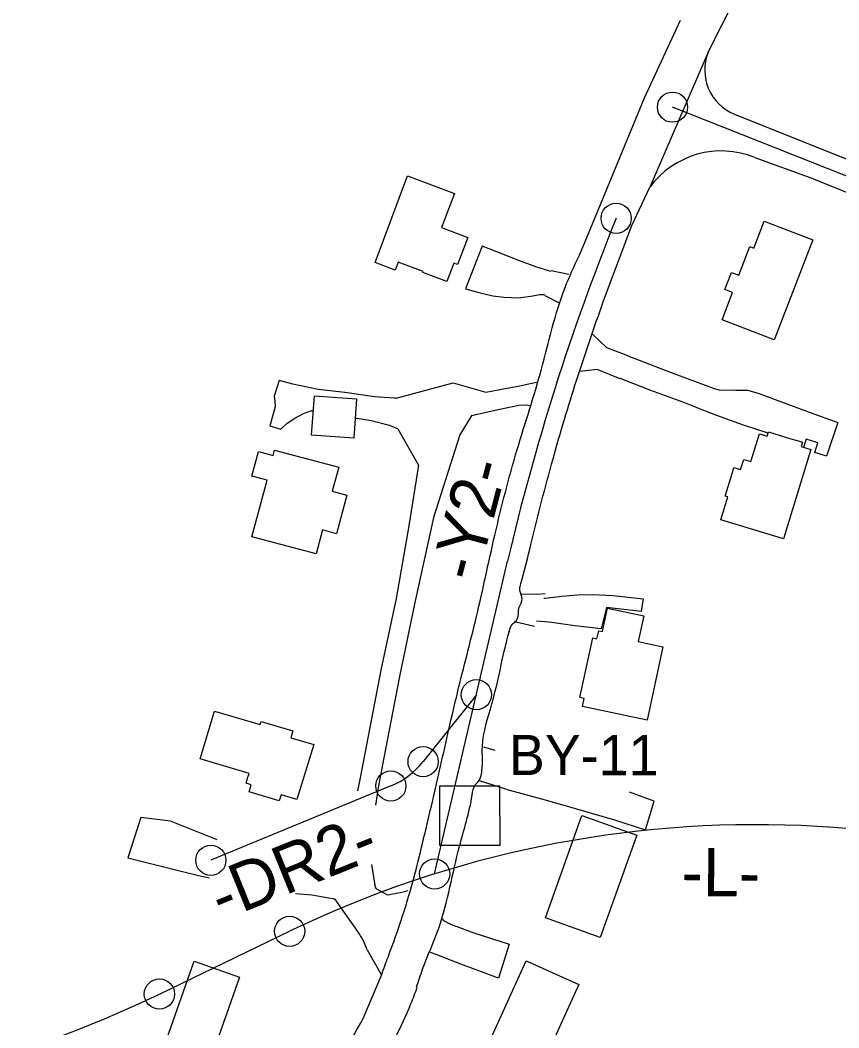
# Model space of a CAD drawing. Extents: x 2088830 to 2093930, y 861854 to 865154.
# Drawn here: x 2091262 to 2091668, y 863895 to 864396 of the extents above; entities that cross this region are included whole.
import ezdxf

# ---------------------------------------------------------------- set-up
doc = ezdxf.new("R2010")
doc.units = 0
for name, color, linetype in [('Default', 7, 'Continuous'), ('Exist Building', 7, 'Continuous'), ('Exist Building Metal Canopy', 7, 'Continuous'), ('Exist Horizontal Alignment', 7, 'Continuous'), ('Exist Horizontal Alignment Station Label', 7, 'Continuous'), ('Exist Roads EOP', 7, 'Continuous'), ('Exist Roads EOP Other', 7, 'Continuous'), ('Exist Roads Soil', 7, 'Continuous')]:
    doc.layers.add(name, color=color, linetype=linetype)

msp = doc.modelspace()

# ---------------------------------------------------------------- linework, layer by layer
at = {"layer": 'Default'}
for p, q in [((2091755.37, 864285.26), (2091585.51, 864352.73)), ((2091467.38, 863971.85), (2091503.59, 864127.14)), ((2091488.13, 864060.86), (2091461.67, 864027.62)), ((2091445.65, 864015.56), (2091356.26, 863978.63)), ((2091484.79, 864000.62), (2091484.79, 864000.62)), ((2091330.74, 863912.18), (2091395.38, 863943.36))]:
    msp.add_line(p, q, dxfattribs=at)
msp.add_lwpolyline([(2091470, 863985.91), (2091469.97, 864015.56), (2091499.67, 864015.59), (2091499.7, 863985.94)], close=True, dxfattribs=at)
for centre, radius, start, end in [((2092628.42, 863864.87), 1155, 158.0015, 166.87501), ((2091430.37, 864052.53), 40, 292.4477, 321.4722), ((2091626.97, 863463.31), 533, 59.4206, 115.7537), ((2091085.24, 864421.06), 565, 247.6724, 295.7537)]:
    msp.add_arc(centre, radius, start, end, dxfattribs=at)
at = {"layer": 'Exist Building'}
for points in [[(2091437.82, 864275.59), (2091453.99, 864318.63), (2091477.26, 864309.88), (2091470.88, 864292.91), (2091483.81, 864288.05), (2091478.73, 864274.54), (2091476.95, 864275.22), (2091473.53, 864266.06), (2091461.46, 864270.57), (2091461.65, 864271.07), (2091449.31, 864275.68), (2091447.87, 864271.83)], [(2091655.14, 864286.85), (2091636.58, 864238.83), (2091635.91, 864237.11), (2091610.12, 864247.08), (2091615.36, 864260.64), (2091611.46, 864262.14), (2091614.76, 864270.67), (2091618.44, 864269.25), (2091623.93, 864283.44), (2091625.88, 864282.69), (2091631.08, 864296.15)], [(2091654.15, 864182.64), (2091640.54, 864138.26), (2091609.57, 864147.75), (2091613.05, 864159.11), (2091611.59, 864159.55), (2091615.04, 864170.83), (2091615.92, 864173.69), (2091619.28, 864172.66), (2091620.84, 864177.77), (2091624.39, 864176.68), (2091628.62, 864190.48), (2091632.57, 864189.27), (2091633.24, 864191.45), (2091644.32, 864188.05), (2091647.42, 864187.1), (2091648.97, 864186.63), (2091650.02, 864186.31), (2091649.34, 864184.11)], [(2091376.68, 864139.32), (2091384.22, 864167.45), (2091376.6, 864169.49), (2091379.87, 864181.67), (2091387.24, 864179.69), (2091387.95, 864182.36), (2091419.75, 864173.86), (2091416.57, 864161.97), (2091423.77, 864160.04), (2091418.64, 864140.85), (2091411.7, 864142.7), (2091408.52, 864130.81)], [(2091580.7, 864084.72), (2091572.92, 864048.23), (2091540.88, 864055.07), (2091541.71, 864058.97), (2091539.54, 864059.42), (2091545.96, 864089.04), (2091547.98, 864088.61), (2091548.84, 864092.6), (2091550.75, 864092.19), (2091553.25, 864103.9), (2091571.23, 864100.04), (2091568.5, 864087.34)], [(2091407.39, 864036.09), (2091399, 864008.77), (2091391.12, 864011.1), (2091390.24, 864008.13), (2091375.31, 864012.58), (2091376.35, 864016.08), (2091373.75, 864016.85), (2091374.68, 864019.97), (2091375.23, 864021.8), (2091351, 864029.01), (2091358.06, 864052.71), (2091380.81, 864045.99), (2091381.26, 864047.53), (2091397.01, 864042.88), (2091395.99, 864039.44)], [(2091567.71, 863991.16), (2091549.56, 863940.28), (2091522.37, 863949.98), (2091540.52, 864000.86)], [(2091370.53, 863920.51), (2091356.89, 863881.93), (2091334.42, 863889.87), (2091348.05, 863928.44)], [(2091538.91, 863916.88), (2091518.47, 863871.7), (2091492.32, 863883.53), (2091512.77, 863928.7)]]:
    msp.add_lwpolyline(points, close=True, dxfattribs=at)
at = {"layer": 'Exist Building Metal Canopy'}
msp.add_lwpolyline([(2091427.19, 864188.24), (2091406.31, 864189.81), (2091407.71, 864209.34), (2091428.59, 864207.77)], close=True, dxfattribs=at)
at = {"layer": 'Exist Horizontal Alignment Station Label'}
for centre in [(2091585.51, 864352.73), (2091557.51, 864297.51), (2091488.13, 864060.86), (2091461.67, 864027.62), (2091445.65, 864015.56), (2091356.26, 863978.63), (2091467.38, 863971.85), (2091395.38, 863943.36), (2091330.74, 863912.18)]:
    msp.add_circle(centre, 7.5, dxfattribs=at)
at = {"layer": 'Exist Roads EOP'}
for p, q in [((2091603.22, 864379.98), (2091633.88, 864440.85)), ((2091571.6, 864357.33), (2091589.51, 864395.95)), ((2091603.22, 864379.98), (2091574.3, 864312.94)), ((2091548.67, 864301.49), (2091571.6, 864357.33)), ((2091565.36, 864293.93), (2091574.3, 864312.94)), ((2091539.24, 864279.17), (2091548.67, 864301.49)), ((2091551.26, 864256.55), (2091565.36, 864293.93)), ((2091431.95, 863899.97), (2091441.17, 863921.92))]:
    msp.add_line(p, q, dxfattribs=at)
msp.add_lwpolyline([(2091504.65, 864092.39), (2091504.6, 864092.26)], dxfattribs=at)
for points in [[(2091441.1, 863921.91), (2091444.26, 863930.54), (2091451.5, 863951.02), (2091462.11, 863990.03), (2091470.34, 864025.4), (2091478.72, 864061.83), (2091488.18, 864099.79), (2091497.28, 864140.14), (2091508.39, 864182.61), (2091520.43, 864222.63), (2091532.13, 864263.12), (2091539.24, 864279.17)], [(2091458.4, 863915.67), (2091461.42, 863924.49), (2091469.42, 863944.94), (2091479.75, 863985.59), (2091486.04, 864011.02), (2091487.65, 864016.26), (2091489.53, 864018.43), (2091490.64, 864021.54), (2091491.12, 864028.71), (2091491.12, 864035.24), (2091495.79, 864056.26), (2091504.17, 864091.54), (2091506.21, 864096.08), (2091508.03, 864097.81), (2091509.43, 864104.3), (2091510.9, 864108.46), (2091509.69, 864112.64), (2091510.21, 864116.03), (2091515.22, 864135.56), (2091526.19, 864178.07), (2091537.83, 864216.97), (2091551.26, 864256.55)], [(2090168.38, 864198.76), (2090189.5, 864189.72), (2090230.53, 864172.75), (2090273.59, 864155.99), (2090314.47, 864138.57), (2090356.17, 864122.11), (2090401.7, 864102.94), (2090442.19, 864087.09), (2090481.45, 864070.2), (2090523.64, 864052.97), (2090568.11, 864034.48), (2090610.4, 864017.13), (2090655.12, 863999.01), (2090697.83, 863981.77), (2090742.36, 863964.54), (2090779.16, 863949.36), (2090823.64, 863930.17), (2090867.73, 863911.82), (2090910.45, 863894.46), (2090950.82, 863877.93), (2090971.61, 863869.44), (2091006.7, 863856.03), (2091045.62, 863839.26), (2091086.07, 863822.83), (2091122.3, 863807.64), (2091162.46, 863791.02), (2091203.94, 863773.83), (2091243.88, 863757.78), (2091278.52, 863743.03), (2091290.86, 863741.47), (2091305.69, 863743.45)], [(2090159.86, 864177.45), (2090180.67, 864168.73), (2090222.86, 864151.65), (2090264.39, 864134.6), (2090306, 864117.79), (2090347.24, 864101.05), (2090392.99, 864082.57), (2090433.2, 864065.09), (2090472.83, 864048.96), (2090514.73, 864032.43), (2090559.97, 864014.05), (2090601.37, 863997.19), (2090646.29, 863978.82), (2090688.95, 863961.27), (2090733.38, 863942.96), (2090770.05, 863927.33), (2090814.52, 863908.72), (2090858.91, 863891), (2090901.15, 863874.17), (2090939.87, 863858.28), (2090962.72, 863848.64), (2090997.54, 863834.72), (2091036.07, 863819.08), (2091075.6, 863802.48), (2091112.88, 863787.77), (2091153.64, 863770.65), (2091194.67, 863753.49), (2091234.07, 863737.23), (2091276.57, 863719.33), (2091296.56, 863710.75), (2091332.88, 863695.67), (2091370.71, 863680.05), (2091411.45, 863662.85), (2091427.01, 863655.9), (2091440.19, 863646.8), (2091448.83, 863640.62), (2091463.67, 863633.85), (2091467.99, 863632.17), (2091469.11, 863631.07), (2091469.97, 863630.04), (2091470.37, 863629.28)], [(2091458.63, 863915.3), (2091455.43, 863907.16), (2091438.17, 863872.89), (2091417.82, 863841.31), (2091394.13, 863810.14), (2091368.83, 863778.33), (2091355.6, 863760.48), (2091347.95, 863737.92), (2091353.05, 863717.6), (2091353.04, 863717.56), (2091357.07, 863712.82), (2091361.5, 863708.99), (2091398.61, 863693.57), (2091435.17, 863678.96), (2091472.88, 863664.14), (2091513.07, 863651.42), (2091550.28, 863640.44), (2091559.59, 863639.13), (2091561.17, 863638.35), (2091573.07, 863633.85), (2091588.61, 863630.02), (2091610.92, 863627.57), (2091621.33, 863629.04)], [(2091316.71, 863747.76), (2091320.13, 863750.32), (2091334.11, 863765.12), (2091358.4, 863794.91), (2091381.85, 863824.24), (2091385.28, 863828.95), (2091386.17, 863832.05), (2091386.64, 863833.99), (2091391.05, 863839.87), (2091394.85, 863844.48), (2091397.51, 863845.77), (2091399.36, 863846.66), (2091401.03, 863848.65), (2091412.87, 863867.49), (2091431.95, 863899.97)]]:
    msp.add_spline(points, degree=3, dxfattribs=at)
at = {"layer": 'Exist Roads EOP Other'}
for p, q in [((2091534.06, 864269.68), (2091525.31, 864271.36)), ((2091522.18, 864259.21), (2091529.15, 864255.6))]:
    msp.add_line(p, q, dxfattribs=at)
for points in [[(2091525.12, 864271.03), (2091517.61, 864273.43), (2091509.17, 864276.59), (2091494.46, 864282.28), (2091490.97, 864283.61), (2091482.74, 864262.48), (2091489.95, 864260.45), (2091496.29, 864259.07), (2091501.71, 864258.37), (2091509.09, 864258.05), (2091516.09, 864259), (2091519.54, 864259.65), (2091521.64, 864259.69), (2091522.18, 864259.53)], [(2091545.82, 864239.95), (2091552.72, 864233.39), (2091563.63, 864229.22)], [(2091563.62, 864229.05), (2091566.85, 864227.81), (2091583.59, 864221.44), (2091599.02, 864215.64), (2091606.23, 864212.94), (2091608.65, 864212.35), (2091616.92, 864212.14), (2091622.67, 864212.23), (2091628, 864210.59), (2091653.79, 864201.08), (2091667.6, 864196.01), (2091661.98, 864179.38), (2091656.19, 864181.17), (2091657.69, 864186.04), (2091651.87, 864187.83), (2091650.61, 864183.72)], [(2091559.56, 864217.75), (2091548.16, 864222.36), (2091539.43, 864221.45)], [(2091632.96, 864190.71), (2091620.8, 864194.7), (2091611.94, 864197.99), (2091603.5, 864201.09), (2091591.09, 864206.04), (2091574.8, 864212.04), (2091561.68, 864217.15), (2091559.7, 864217.97)]]:
    msp.add_lwpolyline(points, dxfattribs=at)
at = {"layer": 'Exist Roads Soil'}
for p, q in [((2091616.34, 864349.21), (2091761.96, 864290.93)), ((2091626.32, 864327.69), (2091654.68, 864317.48)), ((2091654.68, 864317.48), (2091718.07, 864291.58)), ((2091507.69, 864097.09), (2091517.05, 864094.91)), ((2091491.61, 864034.93), (2091497.26, 864033.27)), ((2091502.68, 864013.87), (2091489.74, 864018.08)), ((2091433.81, 863934.16), (2091440.87, 863921.84))]:
    msp.add_line(p, q, dxfattribs=at)
for points in [[(2091447.27, 864208.15), (2091437.46, 864208.85), (2091422.86, 864210.91), (2091409.61, 864212.45), (2091396.9, 864215.21), (2091390.17, 864216.91), (2091387.79, 864209.16), (2091388.04, 864206.63), (2091388.22, 864203.94), (2091385.49, 864194.47), (2091391.01, 864192.77), (2091394.17, 864195.8), (2091398, 864198.28), (2091402.21, 864200.58), (2091405.96, 864201.91), (2091407.18, 864201.96)], [(2091448.26, 864208.12), (2091476.66, 864215.82), (2091492.78, 864211.08)], [(2091492.78, 864211.08), (2091499.7, 864212.47), (2091509.63, 864214.33), (2091516.38, 864215.74), (2091518.09, 864216.15)], [(2091448.26, 864208.12), (2091448.09, 864208.12), (2091447.27, 864208.15)], [(2091485.98, 864199.58), (2091488.55, 864200.15), (2091499.83, 864202.65), (2091509.16, 864204.72), (2091513.39, 864204.84), (2091514.5, 864204.58)], [(2091427.92, 864198.39), (2091428.95, 864198.14)], [(2091449.09, 864192.9), (2091444.92, 864194.55), (2091435.93, 864196.9), (2091428.95, 864198.14)], [(2091485.82, 864199.68), (2091479.84, 864189.88), (2091466.83, 864148.87), (2091457.53, 864106.62), (2091449.87, 864069.96), (2091439.63, 864016.58), (2091437.96, 864006.08)], [(2091449.09, 864192.9), (2091459.37, 864174.96)], [(2091459.37, 864174.96), (2091454.53, 864144.81), (2091448.34, 864108.66), (2091440.65, 864073.02), (2091430.46, 864019.64), (2091429.11, 864013.06)], [(2091522.27, 864110.91), (2091518.43, 864110.59), (2091510.47, 864110.87)], [(2091521.63, 864108.89), (2091522.06, 864108.85), (2091530.64, 864109.86), (2091538.25, 864110.51), (2091545.68, 864110.63), (2091556.03, 864110.23), (2091570.96, 864108.54), (2091569.9, 864102.16), (2091552.66, 864104.23), (2091550.04, 864093.53), (2091537.07, 864095.09), (2091524.18, 864096.83), (2091517.89, 864097.46)], [(2091502.68, 864013.87), (2091522.33, 864008.57), (2091537.77, 864004.24), (2091556.66, 863998.69), (2091572.06, 863993.67), (2091576.44, 864007.92), (2091564.17, 864012.49)], [(2091359.34, 863988.85), (2091336.21, 863998.07), (2091321.49, 863999.9), (2091315.08, 863979.88), (2091350.22, 863971), (2091355.53, 863969.92)], [(2091436, 863976.48), (2091437.65, 863966.23)], [(2091398.34, 863962.13), (2091406.39, 863961.4), (2091417.61, 863959.47), (2091429.14, 863943.23)], [(2091443.81, 863961.5), (2091438.34, 863964.46), (2091437.65, 863966.23)], [(2091417.63, 863959.27), (2091417.28, 863959.39)], [(2091471.1, 863949.52), (2091471.86, 863948.68), (2091475.2, 863946.86), (2091486.93, 863942.63), (2091504.32, 863936.92), (2091499.13, 863919.99), (2091480.46, 863927), (2091468.12, 863931.77), (2091465.3, 863932.81)]]:
    msp.add_lwpolyline(points, dxfattribs=at)
for centre, radius, start, end in [((2091625.16, 864371.15), 23.65, 158.0994, 248.0994), ((2091609.69, 864287.22), 43.76, 67.6724, 143.9886)]:
    msp.add_arc(centre, radius, start, end, dxfattribs=at)
for centre, major_axis, ratio, start_param, end_param in [((2091436.1, 864007.48), (62.63, 5.64), 0.740396, 4.76902, 4.940315), ((2091407.82, 863926.63), (26.8, 3.75), 0.993351, 0.143802, 0.525366)]:
    msp.add_ellipse(centre, major_axis=major_axis, ratio=ratio, start_param=start_param, end_param=end_param, dxfattribs=at)

# ---------------------------------------------------------------- texts
at = {"layer": 'Default'}
msp.add_text('BY-11', height=20, rotation=359.942, dxfattribs=at).set_placement((2091504.25, 864020.94))
at = {"layer": 'Exist Horizontal Alignment'}
for s, rotation, p in [('-Y2-', 75.3196, (2091488.35, 864116.2)), ('-DR2-', 22.0394, (2091361.65, 863948.39)), ('-L-', 359.5505, (2091589.8, 863960.86))]:
    msp.add_text(s, height=24, rotation=rotation, dxfattribs=at).set_placement(p)

doc.saveas('drawing.dxf')
